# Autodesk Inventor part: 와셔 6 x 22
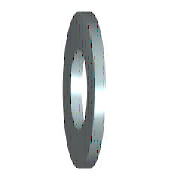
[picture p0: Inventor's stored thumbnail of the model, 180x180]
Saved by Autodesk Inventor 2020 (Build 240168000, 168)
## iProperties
Created: 2012-02
Part Number: 와셔 6 x 22
Material: 강철
Description: 평면 와셔 - 초대형 시리즈 - 제품 등급 C
Document SubType Name: Modeling
Standard: ISO 7094
Designer: mdu-01
Standard Revision: Second edition 2000-06-01
Standards Organization: ISO
Language: ko-KR
Size Designation: ST 6 - 100 HV
Categories: <MemberInstance><Categories><Category DisplayName="조임쇠" InternalName="e4da775c-781d-43d5-af7c-5136215cf5a6" Mnemonic="FSTN"><Category DisplayName="와셔" InternalN
Density: 7.85 g/cm^3
Appearance: 파란색 - 벽 페인트 - 광택
IsCustomPart: 1
Author: mdu-01
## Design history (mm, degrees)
sketch "스케치"
  geometry: C1 r 11 at (0, 0); C2 r 3.3 at (0, 0); 1 further point
  constraints: 2 centre point, 2 coincident
  dimensions: "d0" = 6.6 diameter of C2 (= SD1); "d1" = 22 diameter of C1 (= SD2)
extrude "본체" new body sketch "스케치" distance "d2" = 2 (= SD); taper "d3" = 0 deg
workaxis "Work Axis1"
workplane "Work Plane1"
body "Solid1"
other parameters: "SD1" = 6.6 [user parameter; used in 1 equation term], "SD2" = 22 [user parameter; used in 1 equation term], "SD" = 2 [user parameter; used in 1 equation term], "d4" = 0, "d5" = 0, "d6" = 0, "d7" = 0, "NND" = 6 [user parameter]
